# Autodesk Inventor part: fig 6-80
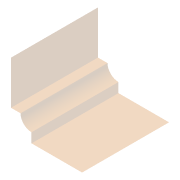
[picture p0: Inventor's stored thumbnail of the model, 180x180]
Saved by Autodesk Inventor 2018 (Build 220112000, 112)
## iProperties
Shininess: 64.0
Length Units: 11269
Angle Units: 11279
Time Units: 11290
Mass Units: 11283
Length Display Precision: 3
Angle Display Precision: 2
Compacted: True
Part Number: fig 6-80
Document SubType Name: Modeling
Created: 2003-10
Designer: Owner
Manufacturer: Standard
Standards Organization: Custom
Density: 1 g/cm^3
Material: Generic
Appearance: Default
Density: 0.0
Volumn: 0.0
Area: 0.0
PropertySet Name: Model Information
Control State: 0
Master: False
Checked Out: False
Author: Owner
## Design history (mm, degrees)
node "Sketch1"
sketch "Sketch2"
  geometry: L1 (22.777, 31.862)-(22.777, 0.2); L2 (7.777, -14.8)-(-29.161, -14.8); A1 r 15 centre (7.777, 0.2) between (7.777, -14.8) and (22.777, 0.2)
  constraints: 4 end point, 2 point on circle, 2 tangent, 1 centre point, 1 perpendicular, 1 vertical
  dimensions: "d23" = 15 radius of A1
extrude_surface "ExtrusionSrf1" sketch "Sketch2" dims "d24" = 63.5, "d25" = 0
feature "OffsetSrf12" dims "d31" = 7, "d32" = 1
body "Solid1"
body "Srf1"
